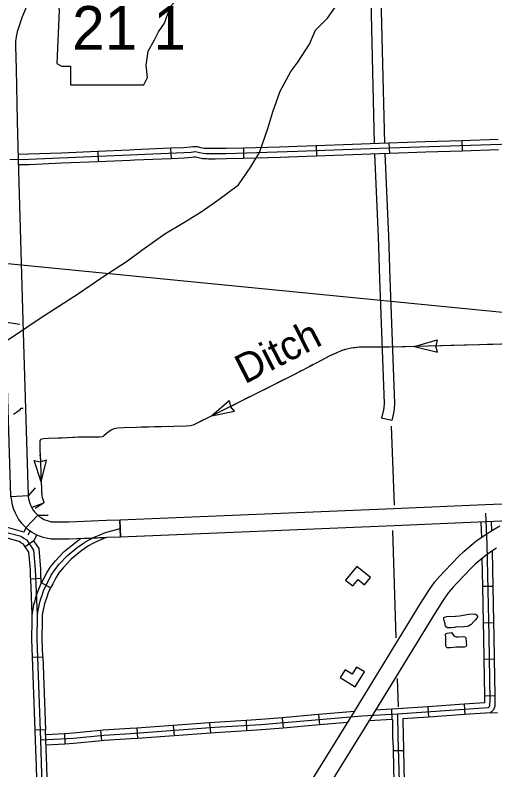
# Model space of a CAD drawing. Extents: x 1164457 to 1439835, y 1590918 to 1773502.
# Drawn here: x 1255743 to 1262694, y 1630223 to 1641151 of the extents above; entities that cross this region are included whole.
import ezdxf

# ---------------------------------------------------------------- set-up
doc = ezdxf.new("R2010")
doc.units = 0
for name, color, linetype in [('Level 10', 7, 'Continuous'), ('Level 15', 7, 'Continuous'), ('Level 21', 7, 'Continuous'), ('Level 31', 7, 'Continuous'), ('Level 32', 7, 'Continuous'), ('Level 35', 7, 'Continuous'), ('Level 37', 7, 'Continuous'), ('Level 43', 7, 'Continuous'), ('Level 45', 7, 'Continuous'), ('Level 46', 7, 'Continuous'), ('Level 5', 7, 'Continuous'), ('Level 58', 7, 'Continuous'), ('R_Draft', 7, 'Continuous')]:
    doc.layers.add(name, color=color, linetype=linetype)

msp = doc.modelspace()

# ---------------------------------------------------------------- linework, layer by layer
at = {"layer": 'Level 10'}
msp.add_line((1255902, 1633728), (1255900, 1633729), dxfattribs=at)
msp.add_line((1255902, 1633728), (1255900, 1633729), dxfattribs=at)
for points in [[(1256356, 1642464), (1255941, 1641352), (1255847, 1641124)], [(1255933, 1634192), (1255683, 1634177), (1255683, 1634182), (1255613, 1636388), (1255540, 1639052), (1255523, 1639608), (1255507, 1640363), (1255498, 1640706), (1255500, 1640783), (1255507, 1640833), (1255508, 1640838), (1255509, 1640872), (1255535, 1640977), (1255613, 1641211)], [(1255847, 1641124), (1255775, 1640907), (1255758, 1640838), (1255758, 1640827), (1255756, 1640809), (1255750, 1640762), (1255748, 1640706), (1255757, 1640369), (1255773, 1639615), (1255790, 1639060), (1255863, 1636395), (1255933, 1634192)], [(1255933, 1634192), (1255939, 1634148), (1255943, 1634131), (1255957, 1634084), (1255973, 1634047), (1255988, 1634018), (1256006, 1633983), (1256023, 1633961), (1256072, 1633911)], [(1255683, 1634177), (1255694, 1634094), (1255697, 1634085), (1255703, 1634063), (1255722, 1633999), (1255746, 1633943), (1255765, 1633904), (1255795, 1633848), (1255831, 1633800), (1255902, 1633728)], [(1257261, 1633845), (1261223, 1634007), (1262554, 1634064), (1263406, 1634101), (1263762, 1634104)], [(1263762, 1634104), (1263437, 1634027), (1263120, 1633919), (1262906, 1633829), (1262564, 1633814), (1261234, 1633757), (1257271, 1633595), (1257261, 1633845)], [(1255900, 1633729), (1256072, 1633911), (1256090, 1633894), (1256094, 1633891), (1256124, 1633872), (1256162, 1633850), (1256223, 1633828), (1256268, 1633816), (1256283, 1633814), (1256521, 1633814), (1257067, 1633837), (1257261, 1633845), (1257271, 1633595)], [(1257271, 1633595), (1257077, 1633587), (1256526, 1633564), (1256266, 1633564), (1256219, 1633571), (1256150, 1633589), (1256056, 1633622), (1255993, 1633659), (1255953, 1633685), (1255931, 1633701), (1255902, 1633728)]]:
    msp.add_lwpolyline(points, dxfattribs=at)
at = {"layer": 'Level 15'}
for points in [[(1259495, 1629193), (1260659, 1631068), (1261616, 1632631), (1261748, 1632836), (1261825, 1632945), (1261896, 1633029), (1261968, 1633106), (1262172, 1633318), (1262242, 1633386), (1262385, 1633505), (1262433, 1633543), (1262508, 1633596), (1262577, 1633641), (1262619, 1633669), (1262682, 1633709), (1262764, 1633755)], [(1262715, 1633433), (1262649, 1633389), (1262583, 1633343), (1262542, 1633311), (1262409, 1633200), (1262349, 1633142), (1262149, 1632933), (1262083, 1632863), (1262023, 1632792), (1261955, 1632696), (1261828, 1632498), (1260872, 1630937), (1259708, 1629061)]]:
    msp.add_lwpolyline(points, dxfattribs=at)
at = {"layer": 'Level 21'}
msp.add_lwpolyline([(1256307, 1641730), (1256383, 1641222), (1256349, 1640452), (1256417, 1640410), (1256544, 1640410), (1256544, 1640139), (1257610, 1640139), (1257661, 1640249), (1257644, 1640427), (1257669, 1640630), (1257762, 1640791), (1257821, 1640909), (1257906, 1641036), (1257957, 1641171), (1257999, 1641281), (1258075, 1641374), (1258092, 1641434), (1258058, 1641476), (1257796, 1641476), (1257855, 1641594), (1257864, 1641670), (1257829, 1641729)], close=True, dxfattribs=at)
at = {"layer": 'Level 31'}
for p, q in [((1256256, 1632857), (1256125, 1632930)), ((1256256, 1632857), (1256125, 1632930)), ((1255996, 1631854), (1256146, 1631859)), ((1256185, 1630804), (1256035, 1630799))]:
    msp.add_line(p, q, dxfattribs=at)
for points in [[(1256174, 1628690), (1256116, 1630653), (1256062, 1632115), (1256067, 1632458), (1256073, 1632505), (1256090, 1632602), (1256104, 1632651), (1256118, 1632700), (1256136, 1632754), (1256155, 1632816), (1256182, 1632879), (1256223, 1632952), (1256266, 1633041), (1256318, 1633120), (1256384, 1633201), (1256503, 1633329), (1256643, 1633443), (1256719, 1633498), (1256778, 1633536), (1256825, 1633561), (1256888, 1633593), (1256959, 1633624), (1257054, 1633661), (1257266, 1633720)], [(1256440, 1633371), (1256452, 1633384), (1256598, 1633502), (1256692, 1633571), (1257062, 1633587)], [(1257062, 1633587), (1256920, 1633525), (1256859, 1633494), (1256816, 1633471), (1256762, 1633436), (1256689, 1633383), (1256554, 1633274), (1256550, 1633269)], [(1256125, 1632930), (1256156, 1632986), (1256201, 1633077), (1256257, 1633164), (1256327, 1633250), (1256440, 1633371)], [(1256550, 1633269), (1256440, 1633151), (1256378, 1633076), (1256332, 1633004), (1256289, 1632917), (1256256, 1632857)], [(1255991, 1632386), (1255993, 1632463), (1255999, 1632516), (1256016, 1632619), (1256032, 1632672), (1256046, 1632722), (1256065, 1632777), (1256085, 1632842), (1256115, 1632912), (1256125, 1632930)], [(1256141, 1632383), (1256142, 1632453), (1256147, 1632495), (1256163, 1632585), (1256176, 1632630), (1256189, 1632677), (1256207, 1632731), (1256226, 1632790), (1256250, 1632846), (1256256, 1632857)], [(1255996, 1631854), (1255987, 1632114), (1255991, 1632386)], [(1256146, 1631859), (1256137, 1632116), (1256141, 1632383)], [(1256016, 1631326), (1255996, 1631854)], [(1256146, 1631859), (1256166, 1631332)], [(1256035, 1630799), (1256016, 1631326)], [(1256166, 1631332), (1256185, 1630804)], [(1256202, 1630276), (1256191, 1630655), (1256185, 1630804)], [(1256052, 1630271), (1256041, 1630650), (1256035, 1630799)], [(1256068, 1629744), (1256052, 1630271)], [(1256218, 1629748), (1256202, 1630276)]]:
    msp.add_lwpolyline(points, dxfattribs=at)
at = {"layer": 'Level 32'}
for p, q in [((1256014, 1633539), (1255891, 1633453)), ((1256119, 1632992), (1255969, 1632986)), ((1262515, 1632882), (1262665, 1632885)), ((1262526, 1632354), (1262676, 1632357)), ((1262535, 1631826), (1262685, 1631829)), ((1262543, 1631298), (1262693, 1631301)), ((1261721, 1631137), (1261731, 1630988)), ((1262248, 1631174), (1262258, 1631024)), ((1260140, 1631024), (1260153, 1630875)), ((1261195, 1631102), (1261203, 1630952)), ((1259089, 1630939), (1259098, 1630789)), ((1259614, 1630979), (1259627, 1630829)), ((1257508, 1630828), (1257519, 1630679)), ((1258035, 1630867), (1258046, 1630717)), ((1258561, 1630905), (1258572, 1630755)), ((1256457, 1630747), (1256465, 1630597)), ((1256980, 1630793), (1256994, 1630643)), ((1261221, 1630503), (1261371, 1630506))]:
    msp.add_line(p, q, dxfattribs=at)
for points in [[(1254037, 1636839), (1254355, 1636851), (1254649, 1636851), (1255814, 1636677)], [(1262559, 1633939), (1262578, 1633493), (1262604, 1632158), (1262619, 1631228), (1262617, 1631160), (1262609, 1631134), (1262596, 1631122), (1261285, 1631032), (1260766, 1631002), (1259307, 1630877), (1258636, 1630835), (1257417, 1630747), (1257027, 1630722), (1256590, 1630680), (1256116, 1630653)], [(1262489, 1633811), (1262499, 1633590)], [(1262639, 1633817), (1262645, 1633686)], [(1256040, 1633123), (1256017, 1633403), (1255916, 1633547), (1255863, 1633579), (1255842, 1633594), (1255830, 1633600), (1255624, 1633656), (1255335, 1633642)], [(1255868, 1633667), (1255633, 1633732), (1255470, 1633724)], [(1255868, 1633667), (1255902, 1633728)], [(1255931, 1633626), (1255961, 1633680)], [(1255891, 1633453), (1255864, 1633491), (1255821, 1633516), (1255804, 1633529), (1255616, 1633581), (1255478, 1633574)], [(1256014, 1633539), (1256056, 1633622)], [(1256119, 1632992), (1256117, 1633020), (1256115, 1633127), (1256090, 1633430), (1256014, 1633539)], [(1255969, 1632986), (1255967, 1633015), (1255965, 1633119), (1255944, 1633377), (1255891, 1633453)], [(1262655, 1633394), (1262665, 1632885)], [(1262507, 1633282), (1262515, 1632882)], [(1256066, 1632462), (1256042, 1633018), (1256040, 1633123)], [(1255991, 1632472), (1255969, 1632986)], [(1256121, 1632927), (1256119, 1632992)], [(1262515, 1632882), (1262526, 1632354)], [(1262665, 1632885), (1262676, 1632357)], [(1262526, 1632354), (1262529, 1632157), (1262535, 1631826)], [(1262676, 1632357), (1262679, 1632159), (1262685, 1631829)], [(1262535, 1631826), (1262543, 1631298)], [(1262685, 1631829), (1262693, 1631301)], [(1262543, 1631298), (1262544, 1631229), (1262543, 1631194), (1262248, 1631174)], [(1262693, 1631301), (1262694, 1631228), (1262691, 1631147), (1262674, 1631092), (1262627, 1631049), (1262258, 1631024)], [(1261721, 1631137), (1261281, 1631107), (1261195, 1631102)], [(1262248, 1631174), (1261721, 1631137)], [(1260140, 1631024), (1259614, 1630979)], [(1260660, 1631069), (1260140, 1631024)], [(1261195, 1631102), (1260965, 1631089)], [(1261285, 1631032), (1261288, 1630705), (1261295, 1630548), (1261306, 1630051)], [(1262258, 1631024), (1261731, 1630988)], [(1259089, 1630939), (1258631, 1630910), (1258561, 1630905)], [(1259614, 1630979), (1259301, 1630952), (1259089, 1630939)], [(1260561, 1630910), (1260153, 1630875)], [(1261211, 1630953), (1260870, 1630933)], [(1261211, 1630953), (1261213, 1630703), (1261220, 1630545), (1261221, 1630503)], [(1261731, 1630988), (1261361, 1630962)], [(1261361, 1630962), (1261363, 1630707), (1261370, 1630551), (1261371, 1630506)], [(1257508, 1630828), (1257412, 1630821), (1257021, 1630797), (1256980, 1630793)], [(1258035, 1630867), (1257508, 1630828)], [(1258561, 1630905), (1258035, 1630867)], [(1259627, 1630829), (1259312, 1630802), (1259098, 1630789)], [(1260153, 1630875), (1259627, 1630829)], [(1256457, 1630747), (1256188, 1630732)], [(1256980, 1630793), (1256584, 1630754), (1256457, 1630747)], [(1258046, 1630717), (1257519, 1630679)], [(1258572, 1630755), (1258046, 1630717)], [(1259098, 1630789), (1258641, 1630760), (1258572, 1630755)], [(1256465, 1630597), (1256193, 1630582)], [(1256994, 1630643), (1256596, 1630605), (1256465, 1630597)], [(1257519, 1630679), (1257422, 1630672), (1257033, 1630647), (1256994, 1630643)], [(1261221, 1630503), (1261231, 1630048), (1261235, 1629973)], [(1261371, 1630506), (1261381, 1630054), (1261385, 1629980)]]:
    msp.add_lwpolyline(points, dxfattribs=at)
at = {"layer": 'Level 35'}
for points in [[(1262168, 1632292), (1262137, 1632293), (1262107, 1632287), (1262063, 1632280), (1262028, 1632278), (1262008, 1632280), (1261994, 1632288), (1261979, 1632308), (1261974, 1632324), (1261972, 1632336), (1261968, 1632354), (1261966, 1632375), (1261955, 1632398), (1261955, 1632412), (1261956, 1632429), (1261966, 1632436), (1261996, 1632444), (1262122, 1632447), (1262179, 1632453)], [(1262179, 1632453), (1262319, 1632476), (1262396, 1632482), (1262413, 1632479), (1262427, 1632466), (1262441, 1632447), (1262442, 1632432), (1262430, 1632416), (1262411, 1632398), (1262390, 1632374), (1262350, 1632328), (1262313, 1632302), (1262291, 1632299), (1262243, 1632293), (1262168, 1632292)], [(1262216, 1632001), (1262140, 1631999), (1262096, 1631994), (1262049, 1631990), (1262021, 1631990), (1262004, 1631990), (1261991, 1632001), (1261985, 1632019), (1261982, 1632134), (1261979, 1632186), (1261985, 1632194), (1262005, 1632203), (1262036, 1632210)], [(1262036, 1632210), (1262065, 1632213), (1262085, 1632184), (1262103, 1632161), (1262131, 1632148), (1262169, 1632148), (1262238, 1632155), (1262260, 1632151), (1262273, 1632137), (1262280, 1632079), (1262284, 1632030), (1262280, 1632015), (1262271, 1632006), (1262255, 1632001), (1262216, 1632001)]]:
    msp.add_lwpolyline(points, dxfattribs=at)
at = {"layer": 'Level 37'}
for points in [[(1256032, 1634305), (1255933, 1634192)], [(1256074, 1633909), (1256224, 1633912)], [(1255900, 1633729), (1255900, 1633729)]]:
    msp.add_lwpolyline(points, dxfattribs=at)
at = {"layer": 'Level 43'}
for p, q in [((1261529, 1636352), (1261858, 1636450)), ((1261858, 1636450), (1261837, 1636361)), ((1261529, 1636352), (1261863, 1636272)), ((1261863, 1636272), (1261837, 1636359))]:
    msp.add_line(p, q, dxfattribs=at)
for points in [[(1255485, 1636354), (1255776, 1636543), (1256090, 1636753), (1256664, 1637121), (1257000, 1637352), (1257373, 1637592), (1257579, 1637748), (1257915, 1637986), (1258190, 1638146), (1258439, 1638302), (1258680, 1638473), (1258982, 1638695), (1259158, 1638952), (1259284, 1639162), (1259405, 1639510), (1259478, 1639749), (1259584, 1640047), (1259739, 1640334), (1259840, 1640468), (1260006, 1640728), (1260096, 1640934), (1260268, 1641107), (1260387, 1641271)], [(1263822, 1636377), (1263803, 1636400), (1263788, 1636413), (1263765, 1636418), (1263245, 1636396), (1262470, 1636377), (1261164, 1636342)], [(1262453, 1636377), (1262057, 1636366)], [(1262981, 1636390), (1262585, 1636380)], [(1261164, 1636342), (1260729, 1636341), (1260645, 1636333), (1260610, 1636328), (1260528, 1636309), (1260468, 1636291), (1260405, 1636262), (1260303, 1636217), (1260113, 1636118), (1259760, 1635932), (1258324, 1635214), (1258285, 1635206), (1258228, 1635201), (1257320, 1635176), (1257234, 1635170), (1257205, 1635166), (1257176, 1635159), (1257143, 1635146), (1257107, 1635124), (1257067, 1635093), (1257029, 1635059), (1257019, 1635050), (1257004, 1635043), (1256966, 1635039), (1256685, 1635038)], [(1260671, 1636335), (1260645, 1636333), (1260610, 1636328), (1260528, 1636309), (1260478, 1636294)], [(1260869, 1636341), (1260729, 1636341), (1260671, 1636335)], [(1261058, 1636341), (1261001, 1636341)], [(1261397, 1636348), (1261209, 1636343)], [(1261925, 1636363), (1261529, 1636352)], [(1260357, 1636241), (1260303, 1636217), (1260113, 1636118), (1260005, 1636061)], [(1259888, 1636000), (1259760, 1635932), (1259535, 1635820)], [(1259417, 1635761), (1259063, 1635584)], [(1258591, 1635348), (1258844, 1635573), (1258862, 1635483)], [(1258945, 1635525), (1258591, 1635348)], [(1255718, 1635372), (1255765, 1635401), (1255815, 1635442), (1255832, 1635459), (1255858, 1635462)], [(1258591, 1635348), (1258923, 1635415), (1258862, 1635483)], [(1258473, 1635289), (1258324, 1635214), (1258285, 1635206), (1258228, 1635201), (1258095, 1635197)], [(1257436, 1635180), (1257320, 1635176), (1257234, 1635170), (1257205, 1635166), (1257176, 1635159), (1257143, 1635146), (1257107, 1635124), (1257067, 1635093), (1257062, 1635089)], [(1257765, 1635188), (1257568, 1635183)], [(1257963, 1635194), (1257765, 1635188)], [(1256685, 1635038), (1256655, 1635038), (1256501, 1635030), (1256228, 1635023), (1256156, 1635017), (1256127, 1635012), (1256114, 1635005), (1256109, 1634999), (1256100, 1634983), (1256100, 1634961), (1256101, 1634928), (1256100, 1634854), (1256110, 1634702), (1256116, 1634501), (1256129, 1634184), (1256134, 1634167), (1256159, 1634102), (1256158, 1634093), (1256157, 1634086), (1256033, 1634006)], [(1256419, 1635028), (1256228, 1635023), (1256156, 1635017), (1256127, 1635012), (1256114, 1635005), (1256109, 1634999), (1256100, 1634983), (1256100, 1634961), (1256101, 1634928), (1256101, 1634920)], [(1256947, 1635039), (1256685, 1635038), (1256655, 1635038), (1256551, 1635032)], [(1256104, 1634788), (1256110, 1634702), (1256116, 1634501), (1256120, 1634393)], [(1256120, 1634393), (1256022, 1634702), (1256111, 1634682)], [(1256120, 1634393), (1256198, 1634709), (1256111, 1634682)], [(1256126, 1634261), (1256129, 1634184), (1256134, 1634167), (1256159, 1634102), (1256158, 1634093), (1256157, 1634086), (1255985, 1634022)]]:
    msp.add_lwpolyline(points, dxfattribs=at)
at = {"layer": 'Level 45'}
for p, q in [((1262216, 1639332), (1262220, 1639182)), ((1257996, 1639222), (1258003, 1639072)), ((1259050, 1639225), (1259054, 1639076)), ((1260105, 1639259), (1260110, 1639109)), ((1261160, 1639298), (1261165, 1639148)), ((1256941, 1639176), (1256948, 1639027))]:
    msp.add_line(p, q, dxfattribs=at)
for points in [[(1266436, 1639374), (1266329, 1639400), (1266287, 1639405), (1266199, 1639405), (1262929, 1639280), (1261020, 1639218), (1259834, 1639174), (1258803, 1639143), (1258640, 1639142), (1258548, 1639142), (1258508, 1639143), (1258468, 1639145), (1258415, 1639157), (1258375, 1639168), (1258349, 1639169), (1258324, 1639168), (1258292, 1639163), (1258189, 1639156), (1257406, 1639121), (1255940, 1639060), (1255665, 1639056)], [(1262216, 1639332), (1261688, 1639315)], [(1262743, 1639349), (1262216, 1639332)], [(1257996, 1639222), (1257469, 1639199)], [(1258526, 1639218), (1258512, 1639218), (1258478, 1639220), (1258433, 1639230), (1258387, 1639242), (1258349, 1639244), (1258317, 1639242), (1258284, 1639238), (1258185, 1639231), (1257996, 1639222)], [(1259050, 1639225), (1258802, 1639218), (1258639, 1639217), (1258549, 1639217), (1258526, 1639218)], [(1259577, 1639241), (1259050, 1639225)], [(1260105, 1639259), (1259831, 1639249), (1259577, 1639241)], [(1260632, 1639279), (1260105, 1639259)], [(1261160, 1639298), (1261018, 1639293), (1260632, 1639279)], [(1261688, 1639315), (1261160, 1639298)], [(1256414, 1639154), (1255938, 1639135), (1255788, 1639133)], [(1256941, 1639176), (1256414, 1639154)], [(1257469, 1639199), (1257403, 1639196), (1256941, 1639176)], [(1260110, 1639109), (1259836, 1639099), (1259582, 1639091)], [(1260638, 1639129), (1260110, 1639109)], [(1261165, 1639148), (1261023, 1639143), (1260638, 1639129)], [(1261693, 1639165), (1261165, 1639148)], [(1262220, 1639182), (1261693, 1639165)], [(1262748, 1639199), (1262220, 1639182)], [(1256420, 1639005), (1255942, 1638985), (1255792, 1638983)], [(1256948, 1639027), (1256420, 1639005)], [(1257475, 1639049), (1257410, 1639046), (1256948, 1639027)], [(1258003, 1639072), (1257475, 1639049)], [(1258522, 1639068), (1258505, 1639068), (1258457, 1639071), (1258398, 1639084), (1258364, 1639093), (1258349, 1639094), (1258331, 1639093), (1258300, 1639088), (1258194, 1639081), (1258003, 1639072)], [(1259054, 1639076), (1258805, 1639068), (1258640, 1639067), (1258547, 1639067), (1258522, 1639068)], [(1259582, 1639091), (1259054, 1639076)]]:
    msp.add_lwpolyline(points, dxfattribs=at)
at = {"layer": 'Level 46'}
for points in [[(1261034, 1641793), (1260885, 1641790), (1260944, 1639290)], [(1261034, 1641793), (1261094, 1639296)], [(1260949, 1639141), (1261003, 1637942), (1261023, 1637334), (1261088, 1635530), (1261083, 1635468), (1261080, 1635438), (1261053, 1635316)], [(1261099, 1639146), (1261153, 1637948), (1261173, 1637339), (1261238, 1635528), (1261233, 1635456), (1261229, 1635414), (1261199, 1635283), (1261053, 1635316)], [(1262627, 1631049), (1262733, 1631056)]]:
    msp.add_lwpolyline(points, dxfattribs=at)
at = {"layer": 'Level 5'}
for points in [[(1261192, 1635198), (1261233, 1634057)], [(1261209, 1633691), (1261260, 1632137)], [(1261280, 1631548), (1261294, 1631137)]]:
    msp.add_lwpolyline(points, dxfattribs=at)
at = {"layer": 'Level 58'}
for points in [[(1260693, 1633168), (1260532, 1632971), (1260636, 1632886), (1260712, 1632979), (1260805, 1632904), (1260890, 1633007)], [(1260669, 1631426), (1260803, 1631642), (1260689, 1631712), (1260626, 1631610), (1260523, 1631673), (1260453, 1631559)]]:
    msp.add_lwpolyline(points, close=True, dxfattribs=at)
at = {"layer": 'R_Draft'}
msp.add_line((1283714, 1634794), (1223030, 1640753), dxfattribs=at)

# ---------------------------------------------------------------- texts
at = {"layer": 'Level 21'}
msp.add_text('21 1', height=633, dxfattribs=at).set_placement((1256571, 1640649))
at = {"layer": 'Level 43'}
msp.add_text('Ditch', height=422, rotation=26.9289, dxfattribs=at).set_placement((1259069, 1635803))

doc.saveas('drawing.dxf')
